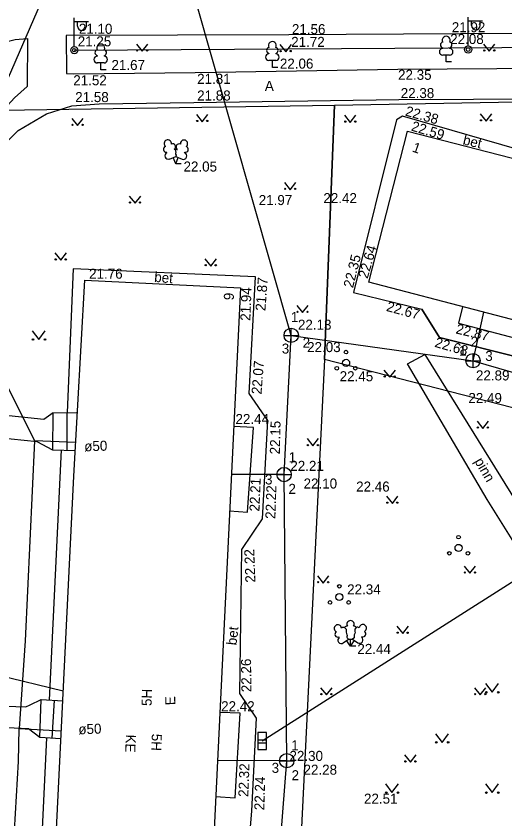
# Model space of a CAD drawing. Extents: x 714391 to 714584, y 6589993 to 6590151.
# Drawn here: x 714456.7 to 714490.9, y 6590036.2 to 6590092.2 of the extents above; entities that cross this region are included whole.
import ezdxf

# ---------------------------------------------------------------- set-up
doc = ezdxf.new("R2010")
doc.units = 0
for name, color, linetype in [('HALJASTUS', 7, 'Continuous'), ('HOONE', 7, 'Continuous'), ('HOONEDET', 7, 'Continuous'), ('KKAEV', 7, 'Continuous'), ('KORGUS', 7, 'Continuous'), ('KTRASS', 7, 'Continuous'), ('MPKAABEL', 7, 'Continuous'), ('POST', 7, 'Continuous'), ('PUU', 7, 'Continuous'), ('TEE', 7, 'Continuous'), ('TORU NR', 7, 'Continuous'), ('VTRASS', 7, 'Continuous'), ('Слой 1', 7, 'Continuous')]:
    doc.layers.add(name, color=color, linetype=linetype)

msp = doc.modelspace()

# ---------------------------------------------------------------- linework, layer by layer
at = {"layer": 'HALJASTUS'}
for p, q in [((714465.147, 6590090.247), (714465.552, 6590089.742)), ((714465.552, 6590089.742), (714465.947, 6590090.247)), ((714475.171, 6590090.202), (714475.576, 6590089.697)), ((714475.576, 6590089.697), (714475.971, 6590090.202)), ((714489.394, 6590090.247), (714489.799, 6590089.742)), ((714489.799, 6590089.742), (714490.194, 6590090.247)), ((714460.632, 6590085.055), (714461.037, 6590084.55)), ((714461.037, 6590084.55), (714461.432, 6590085.055)), ((714469.346, 6590085.326), (714469.751, 6590084.821)), ((714469.751, 6590084.821), (714470.146, 6590085.326)), ((714479.686, 6590085.28), (714480.091, 6590084.775)), ((714480.091, 6590084.775), (714480.486, 6590085.28)), ((714489.169, 6590085.371), (714489.574, 6590084.866)), ((714489.574, 6590084.866), (714489.969, 6590085.371)), ((714475.487, 6590080.584), (714475.892, 6590080.079)), ((714475.892, 6590080.079), (714476.287, 6590080.584)), ((714464.65, 6590079.636), (714465.055, 6590079.131)), ((714465.055, 6590079.131), (714465.45, 6590079.636)), ((714459.458, 6590075.663), (714459.863, 6590075.158)), ((714459.863, 6590075.158), (714460.258, 6590075.663)), ((714469.933, 6590075.256), (714470.338, 6590074.751)), ((714470.338, 6590074.751), (714470.733, 6590075.256)), ((714476.345, 6590072.005), (714476.75, 6590071.5)), ((714476.75, 6590071.5), (714477.145, 6590072.005)), ((714457.867, 6590070.227), (714458.33, 6590069.62)), ((714458.33, 6590069.62), (714458.776, 6590070.227)), ((714482.441, 6590067.49), (714482.846, 6590066.985)), ((714482.846, 6590066.985), (714483.241, 6590067.49)), ((714488.943, 6590063.923), (714489.348, 6590063.418)), ((714489.348, 6590063.418), (714489.743, 6590063.923)), ((714477.067, 6590062.704), (714477.472, 6590062.199)), ((714477.472, 6590062.199), (714477.867, 6590062.704)), ((714482.621, 6590058.685), (714483.026, 6590058.18)), ((714483.026, 6590058.18), (714483.421, 6590058.685)), ((714488.04, 6590053.808), (714488.445, 6590053.303)), ((714488.445, 6590053.303), (714488.84, 6590053.808)), ((714477.79, 6590053.131), (714478.195, 6590052.626)), ((714478.195, 6590052.626), (714478.59, 6590053.131)), ((714483.344, 6590049.609), (714483.749, 6590049.104)), ((714483.749, 6590049.104), (714484.144, 6590049.609)), ((714478.016, 6590045.32), (714478.421, 6590044.815)), ((714478.421, 6590044.815), (714478.816, 6590045.32)), ((714488.762, 6590045.32), (714489.167, 6590044.815)), ((714489.167, 6590044.815), (714489.562, 6590045.32)), ((714489.537, 6590045.607), (714490, 6590045)), ((714490, 6590045), (714490.446, 6590045.607)), ((714486.037, 6590042.107), (714486.5, 6590041.5)), ((714486.5, 6590041.5), (714486.946, 6590042.107)), ((714483.886, 6590040.624), (714484.291, 6590040.119)), ((714484.291, 6590040.119), (714484.686, 6590040.624)), ((714482.537, 6590038.607), (714483, 6590038)), ((714483, 6590038), (714483.446, 6590038.607)), ((714489.537, 6590038.607), (714490, 6590038)), ((714490, 6590038), (714490.446, 6590038.607))]:
    msp.add_line(p, q, dxfattribs=at)
for centre, radius in [((714465.199, 6590089.798), 0.0428), ((714465.899, 6590089.798), 0.0452), ((714475.223, 6590089.752), 0.0428), ((714475.923, 6590089.752), 0.0452), ((714489.446, 6590089.798), 0.0428), ((714490.146, 6590089.798), 0.0452), ((714469.398, 6590084.876), 0.0428), ((714470.098, 6590084.876), 0.0452), ((714489.221, 6590084.921), 0.0428), ((714489.921, 6590084.921), 0.0452), ((714460.684, 6590084.605), 0.0428), ((714461.384, 6590084.605), 0.0452), ((714479.738, 6590084.831), 0.0428), ((714480.438, 6590084.831), 0.0452), ((714475.539, 6590080.135), 0.0428), ((714476.239, 6590080.135), 0.0452), ((714464.702, 6590079.186), 0.0428), ((714465.402, 6590079.186), 0.0452), ((714459.51, 6590075.213), 0.0428), ((714460.21, 6590075.213), 0.0452), ((714469.985, 6590074.807), 0.0428), ((714470.685, 6590074.807), 0.0452), ((714476.397, 6590071.556), 0.0428), ((714477.097, 6590071.556), 0.0452), ((714457.929, 6590069.62), 0.055), ((714458.758, 6590069.62), 0.055), ((714479.793, 6590068.742), 0.125), ((714479.793, 6590067.992), 0.25), ((714479.143, 6590067.617), 0.125), ((714480.443, 6590067.617), 0.125), ((714482.493, 6590067.04), 0.0428), ((714483.193, 6590067.04), 0.0452), ((714488.995, 6590063.473), 0.0428), ((714489.695, 6590063.473), 0.0452), ((714477.119, 6590062.254), 0.0428), ((714477.819, 6590062.254), 0.0452), ((714482.673, 6590058.235), 0.0428), ((714483.373, 6590058.235), 0.0452), ((714487.654, 6590055.825), 0.125), ((714487.654, 6590055.075), 0.25), ((714487.004, 6590054.7), 0.125), ((714488.304, 6590054.7), 0.125), ((714488.092, 6590053.359), 0.0428), ((714488.792, 6590053.359), 0.0452), ((714477.842, 6590052.681), 0.0428), ((714478.542, 6590052.681), 0.0452), ((714479.322, 6590052.398), 0.125), ((714479.322, 6590051.648), 0.25), ((714478.672, 6590051.273), 0.125), ((714479.972, 6590051.273), 0.125), ((714483.396, 6590049.159), 0.0428), ((714484.096, 6590049.159), 0.0452), ((714478.068, 6590044.87), 0.0428), ((714478.768, 6590044.87), 0.0452), ((714488.814, 6590044.87), 0.0428), ((714489.514, 6590044.87), 0.0452), ((714489.599, 6590045), 0.055), ((714490.428, 6590045), 0.055), ((714486.099, 6590041.5), 0.055), ((714486.928, 6590041.5), 0.055), ((714483.938, 6590040.174), 0.0428), ((714484.638, 6590040.174), 0.0452), ((714482.599, 6590038), 0.055), ((714483.428, 6590038), 0.055), ((714489.599, 6590038), 0.055), ((714490.428, 6590038), 0.055)]:
    msp.add_circle(centre, radius, dxfattribs=at)
at = {"layer": 'HOONE'}
for points in [[(714459.73, 6590096.05), (714450.33, 6590074.44), (714440.46, 6590052.39), (714432.7, 6590035.24), (714421.56, 6590009.98), (714417.1, 6590000.12), (714413.783, 6589992.711)], [(714520.618, 6590063.399), (714481.385, 6590073.617), (714484.074, 6590084.17), (714523.648, 6590073.994), (714520.618, 6590063.399)], [(714450.33, 6590074.44), (714452.482, 6590073.562), (714456.5, 6590065.64), (714458.03, 6590062.54), (714457.37, 6590048.6), (714456.96, 6590042.47)], [(714458.41, 6590013.05), (714459.19, 6590027.87), (714460.78, 6590060.09), (714461.543, 6590073.769), (714472.409, 6590073.228), (714469.451, 6590012.441), (714458.41, 6590013.05)], [(714487.937, 6590071.893), (714487.647, 6590070.755), (714491.627, 6590069.716), (714491.916, 6590070.835)], [(714471.651, 6590057.661), (714472.916, 6590057.573), (714473.327, 6590063.471), (714471.938, 6590063.547)], [(714460.88, 6590062.44), (714458.03, 6590062.54)], [(714470.681, 6590037.715), (714472.056, 6590037.636), (714472.394, 6590043.535), (714470.967, 6590043.598)], [(714458.89, 6590022.24), (714455.84, 6590022.32), (714456.07, 6590025.65), (714456.9, 6590040.18), (714456.96, 6590042.47)], [(714456.96, 6590042.47), (714459.9, 6590042.3)]]:
    msp.add_lwpolyline(points, dxfattribs=at)
at = {"layer": 'HOONEDET'}
for points in [[(714458.41, 6590013.05), (714458.331, 6590012.184), (714470.239, 6590011.404), (714470.258, 6590012.413), (714471.076, 6590019.492), (714471.888, 6590019.599), (714472.556, 6590028.807), (714473.199, 6590036.732), (714473.546, 6590043.204), (714472.383, 6590044.92), (714472.511, 6590054.97), (714473.955, 6590057.113), (714474.332, 6590063.959), (714473.026, 6590065.846), (714473.46, 6590073.992), (714460.725, 6590074.548), (714460.31, 6590064.52)], [(714460.86, 6590061.85), (714459.31, 6590061.9), (714459.34, 6590064.51), (714460.97, 6590064.52)], [(714460.3, 6590061.87), (714460.31, 6590064.52)], [(714459.07, 6590044.46), (714459.91, 6590061.92)], [(714459.87, 6590041.74), (714458.41, 6590041.84), (714458.5, 6590044.49), (714460.01, 6590044.41)], [(714459.4, 6590044.44), (714459.24, 6590041.78)], [(714458.06, 6590024.25), (714458.89, 6590041.81)]]:
    msp.add_lwpolyline(points, dxfattribs=at)
at = {"layer": 'KKAEV'}
for p, q in [((714475.96, 6590069.411), (714475.96, 6590070.411)), ((714475.46, 6590069.911), (714476.46, 6590069.911)), ((714488.663, 6590067.645), (714488.663, 6590068.645)), ((714488.163, 6590068.145), (714489.163, 6590068.145)), ((714475.465, 6590059.699), (714475.465, 6590060.699)), ((714474.965, 6590060.199), (714475.965, 6590060.199)), ((714475.65, 6590039.724), (714475.65, 6590040.724)), ((714475.15, 6590040.224), (714476.15, 6590040.224))]:
    msp.add_line(p, q, dxfattribs=at)
for centre in [(714475.96, 6590069.911), (714488.663, 6590068.145), (714475.465, 6590060.199), (714475.65, 6590040.224)]:
    msp.add_circle(centre, 0.5, dxfattribs=at)
at = {"layer": 'KTRASS'}
for p, q in [((714475.96, 6590069.911), (714467.741, 6590098.726)), ((714488.663, 6590068.145), (714489.411, 6590071.527)), ((714475.465, 6590060.199), (714475.96, 6590069.911)), ((714475.96, 6590069.911), (714488.663, 6590068.145)), ((714488.663, 6590068.145), (714507.775, 6590062.609)), ((714475.465, 6590060.199), (714471.775, 6590060.206)), ((714475.65, 6590040.224), (714475.465, 6590060.199)), ((714475.65, 6590040.224), (714470.803, 6590040.234)), ((714474.411, 6590024.03), (714475.65, 6590040.224))]:
    msp.add_line(p, q, dxfattribs=at)
at = {"layer": 'MPKAABEL'}
for points in [[(714460.809, 6590089.818), (714516.791, 6590090.163), (714543.78, 6590090.458), (714574.561, 6590090.139)], [(714558.719, 6590063.793), (714557.614, 6590062.993), (714553.32, 6590062.662), (714527.694, 6590062.802), (714519.691, 6590062.433), (714508.979, 6590063.853), (714473.93, 6590041.599)]]:
    msp.add_lwpolyline(points, dxfattribs=at)
at = {"layer": 'POST'}
for p, q in [((714460.809, 6590090.068), (714460.809, 6590092.068)), ((714460.809, 6590091.818), (714461.809, 6590091.818)), ((714461.036, 6590091.497), (714461.036, 6590091.818)), ((714461.648, 6590091.497), (714461.648, 6590091.818)), ((714488.321, 6590090.113), (714488.321, 6590092.113)), ((714488.321, 6590091.863), (714489.321, 6590091.863)), ((714488.547, 6590091.542), (714488.547, 6590091.863)), ((714489.16, 6590091.542), (714489.16, 6590091.863)), ((714460.809, 6590089.818), (714460.809, 6590089.818)), ((714488.321, 6590089.863), (714488.321, 6590089.863)), ((714474.224, 6590042.198), (714473.627, 6590042.193)), ((714473.627, 6590042.193), (714473.637, 6590040.999)), ((714474.234, 6590041.004), (714474.224, 6590042.198)), ((714473.631, 6590041.677), (714474.228, 6590041.683)), ((714473.633, 6590041.46), (714474.23, 6590041.465)), ((714473.637, 6590040.999), (714474.234, 6590041.004))]:
    msp.add_line(p, q, dxfattribs=at)
for centre, radius in [((714460.809, 6590089.818), 0.25), ((714460.809, 6590089.818), 0.127), ((714488.321, 6590089.863), 0.25), ((714488.321, 6590089.863), 0.127)]:
    msp.add_circle(centre, radius, dxfattribs=at)
for centre in [(714461.342, 6590091.497), (714488.854, 6590091.542)]:
    msp.add_arc(centre, 0.306, 180, 0, dxfattribs=at)
at = {"layer": 'PUU'}
for p, q in [((714486.548, 6590089.975), (714486.548, 6590089.945)), ((714487.028, 6590089.975), (714487.028, 6590089.945)), ((714462.415, 6590089.43), (714462.415, 6590089.4)), ((714462.895, 6590089.43), (714462.895, 6590089.4)), ((714474.405, 6590089.595), (714474.405, 6590089.565)), ((714474.885, 6590089.595), (714474.885, 6590089.565)), ((714487.028, 6590089.47), (714486.548, 6590089.47)), ((714486.788, 6590088.995), (714486.788, 6590089.47)), ((714462.895, 6590088.925), (714462.415, 6590088.925)), ((714462.655, 6590088.45), (714462.655, 6590088.925)), ((714474.885, 6590089.09), (714474.405, 6590089.09)), ((714474.645, 6590088.615), (714474.645, 6590089.09)), ((714487.168, 6590088.995), (714486.788, 6590088.995)), ((714463.035, 6590088.45), (714462.655, 6590088.45)), ((714475.025, 6590088.615), (714474.645, 6590088.615)), ((714467.276, 6590082.664), (714467.261, 6590082.704)), ((714467.806, 6590082.874), (714467.791, 6590082.909)), ((714467.991, 6590082.869), (714468.006, 6590082.909)), ((714468.516, 6590082.654), (714468.531, 6590082.694)), ((714467.451, 6590082.219), (714467.896, 6590082.394)), ((714467.891, 6590081.884), (714467.716, 6590082.324)), ((714467.891, 6590081.884), (714468.071, 6590082.324)), ((714467.896, 6590082.394), (714468.336, 6590082.214)), ((714468.271, 6590081.884), (714467.891, 6590081.884)), ((714479.319, 6590048.831), (714479.294, 6590048.866)), ((714479.594, 6590048.446), (714479.954, 6590048.701)), ((714480.104, 6590048.226), (714479.829, 6590048.611)), ((714479.954, 6590048.701), (714480.249, 6590048.701)), ((714480.104, 6590048.226), (714480.104, 6590048.701)), ((714480.104, 6590048.226), (714480.374, 6590048.616)), ((714480.249, 6590048.701), (714480.609, 6590048.456)), ((714480.879, 6590048.846), (714480.899, 6590048.881)), ((714480.484, 6590048.226), (714480.104, 6590048.226))]:
    msp.add_line(p, q, dxfattribs=at)
for points in [[(714467.896, 6590082.889), (714467.876, 6590082.814), (714467.876, 6590082.794), (714467.886, 6590082.764), (714467.906, 6590082.729), (714467.911, 6590082.709), (714467.896, 6590082.674), (714467.871, 6590082.624), (714467.866, 6590082.599), (714467.871, 6590082.584), (714467.881, 6590082.554), (714467.916, 6590082.494), (714467.921, 6590082.474), (714467.916, 6590082.454), (714467.901, 6590082.419), (714467.896, 6590082.394)], [(714479.689, 6590049.511), (714479.794, 6590049.411), (714479.809, 6590049.381), (714479.809, 6590049.326), (714479.794, 6590049.236), (714479.794, 6590049.191), (714479.814, 6590049.111), (714479.854, 6590049.021), (714479.864, 6590048.976), (714479.859, 6590048.931), (714479.844, 6590048.866), (714479.844, 6590048.836), (714479.864, 6590048.796), (714479.889, 6590048.766), (714479.954, 6590048.701)], [(714480.509, 6590049.526), (714480.414, 6590049.411), (714480.399, 6590049.381), (714480.399, 6590049.326), (714480.414, 6590049.236), (714480.419, 6590049.191), (714480.399, 6590049.111), (714480.359, 6590049.021), (714480.349, 6590048.976), (714480.354, 6590048.931), (714480.369, 6590048.866), (714480.369, 6590048.836), (714480.349, 6590048.796), (714480.324, 6590048.766), (714480.254, 6590048.701)]]:
    msp.add_lwpolyline(points, dxfattribs=at)
for centre, radius, start, end in [((714486.788, 6590090.515), 0.277, 332.5799, 207.4201), ((714462.655, 6590089.97), 0.277, 332.5799, 207.4201), ((714474.455, 6590089.803), 0.212, 105.2441, 257.079), ((714474.645, 6590090.135), 0.277, 332.5799, 207.4201), ((714474.835, 6590089.803), 0.212, 282.921, 74.7559), ((714486.55, 6590089.708), 0.237, 90, 270), ((714486.598, 6590090.183), 0.212, 105.2441, 257.079), ((714487.025, 6590089.708), 0.237, 270, 90), ((714486.978, 6590090.183), 0.212, 282.921, 74.7559), ((714462.417, 6590089.163), 0.237, 90, 270), ((714462.465, 6590089.638), 0.212, 105.2441, 257.079), ((714462.892, 6590089.163), 0.237, 270, 90), ((714462.845, 6590089.638), 0.212, 282.921, 74.7559), ((714474.407, 6590089.328), 0.237, 90, 270), ((714474.882, 6590089.328), 0.237, 270, 90), ((714467.334, 6590083.298), 0.256, 111.5027, 232.5173), ((714467.334, 6590083.298), 0.256, 350.4856, 111.5002), ((714467.677, 6590083.076), 0.202, 305.1345, 116.705), ((714468.124, 6590083.072), 0.202, 62.412, 233.9825), ((714468.47, 6590083.289), 0.256, 67.6168, 188.6314), ((714468.47, 6590083.289), 0.256, 306.5997, 67.6143), ((714467.235, 6590082.902), 0.202, 106.2979, 277.8684), ((714467.365, 6590082.442), 0.237, 111.5014, 291.5004), ((714467.895, 6590082.651), 0.237, 66.7655, 111.5015), ((714468.426, 6590082.434), 0.237, 247.6166, 67.6155), ((714468.563, 6590082.892), 0.202, 261.2486, 72.8191), ((714479.221, 6590049.463), 0.256, 125.5389, 246.5536), ((714479.221, 6590049.463), 0.256, 4.5218, 125.5364), ((714479.866, 6590049.414), 0.202, 84.7965, 150.2995), ((714480.104, 6590049.746), 0.256, 90.0013, 211.0159), ((714480.104, 6590049.746), 0.256, 328.9841, 89.9987), ((714480.341, 6590049.414), 0.202, 34.3857, 95.2035), ((714480.964, 6590049.479), 0.256, 55.522, 176.5367), ((714480.964, 6590049.479), 0.256, 294.5049, 55.5195), ((714479.221, 6590049.054), 0.202, 120.3342, 291.9047), ((714479.607, 6590049.33), 0.202, 65.2382, 130.7412), ((714480.58, 6590049.339), 0.202, 50.3173, 111.1351), ((714480.972, 6590049.07), 0.202, 249.1538, 60.7243), ((714479.458, 6590048.64), 0.237, 125.5377, 305.5366), ((714480.742, 6590048.652), 0.237, 235.5219, 55.5208)]:
    msp.add_arc(centre, radius, start, end, dxfattribs=at)
at = {"layer": 'TEE'}
for points in [[(714573.651, 6590091.235), (714563.941, 6590091.279), (714547.616, 6590091.212), (714515.821, 6590091.083), (714495.803, 6590091.003), (714475.803, 6590090.885), (714460.229, 6590090.83)], [(714439.98, 6590066.01), (714446.14, 6590079.41), (714447.61, 6590082.54), (714448.99, 6590084.86), (714450.43, 6590086.9), (714452.47, 6590088.66), (714455.19, 6590090.19), (714456.67, 6590090.57), (714457.54, 6590090.63)], [(714457.54, 6590090.63), (714457.51, 6590087.28), (714456.63, 6590086.49), (714453.85, 6590083.48), (714451.12, 6590079.51), (714448.27, 6590074.4), (714444.05, 6590065.54), (714439.98, 6590066.01)], [(714460.229, 6590090.83), (714460.256, 6590088.179), (714460.777, 6590088.177), (714469.248, 6590088.252), (714483.421, 6590088.5), (714493.771, 6590088.564), (714493.794, 6590090.794), (714493.796, 6590090.991)], [(714459.34, 6590064.51), (714458.67, 6590064.05), (714447.983, 6590065.15), (714447.715, 6590065.177), (714445.65, 6590065.39), (714446.67, 6590067.85), (714448.36, 6590071.52), (714451, 6590076.28), (714452.73, 6590079.02), (714455.01, 6590082.32), (714456.89, 6590084.2), (714458.87, 6590085.38), (714460.64, 6590085.94), (714462.556, 6590086.069), (714469.16, 6590086.164), (714483.473, 6590086.366), (714493.922, 6590086.42), (714493.109, 6590083.292)], [(714492.924, 6590082.556), (714483.739, 6590085.22), (714483.316, 6590084.953), (714480.306, 6590072.893), (714485.078, 6590071.74), (714486.316, 6590069.766), (714491.895, 6590068.37), (714493.892, 6590069.273), (714504.243, 6590066.794), (714505.962, 6590064.851), (714511.02, 6590063.567), (714513.67, 6590064.358), (714521.189, 6590062.359)], [(714493.892, 6590069.273), (714491.895, 6590068.37), (714486.316, 6590069.766), (714485.078, 6590071.74)], [(714503.783, 6590036.391), (714498.601, 6590044.145), (714494.073, 6590051.394), (714489.657, 6590058.462), (714484.091, 6590067.913), (714485.295, 6590068.584), (714495.449, 6590052.222), (714495.743, 6590051.781), (714495.449, 6590052.222), (714505.314, 6590037.415)], [(714459.31, 6590061.9), (714458.22, 6590062.47), (714447.303, 6590063.601), (714447.271, 6590063.604), (714445.09, 6590063.83), (714436.59, 6590044.66), (714438.563, 6590044.596), (714438.967, 6590044.582), (714457.41, 6590043.98), (714457.72, 6590044.12), (714458.5, 6590044.49)], [(714458.41, 6590041.84), (714457.61, 6590042.45), (714451.01, 6590042.74), (714438.326, 6590043.121), (714437.835, 6590043.135), (714436.01, 6590043.19), (714428.72, 6590026.84), (714430.208, 6590026.691), (714430.977, 6590026.614), (714435.5, 6590026.16), (714448.72, 6590024.98), (714455.07, 6590024.44), (714457.48, 6590024.27)]]:
    msp.add_lwpolyline(points, dxfattribs=at)
at = {"layer": 'VTRASS'}
msp.add_line((714438.963, 6590050.251), (714460.04, 6590045.1), dxfattribs=at)
at = {"layer": 'Слой 1'}
for points in [[(714478.99, 6590085.97), (714532.4, 6590086.95), (714527.28, 6590069.21), (714523.84, 6590056.54), (714478.28, 6590068.22)], [(714455.78, 6590085.63), (714478.99, 6590085.97), (714478.28, 6590068.22), (714475.39, 6590009.54), (714423.1, 6590012.8)]]:
    msp.add_lwpolyline(points, close=True, dxfattribs=at)

# ---------------------------------------------------------------- texts
at = {"layer": 'HOONE'}
for s, rotation, p in [('1', 340.7456, (714484.367, 6590082.753)), ('9', 86.33, (714471.939, 6590072.344)), ('5H', 88.5478, (714466.207, 6590044.034)), ('E', 91.6372, (714467.87, 6590044.105)), ('KE', 267.5848, (714464.415, 6590042.061)), ('5H', 267.5848, (714466.228, 6590042.117))]:
    msp.add_text(s, height=0.7, rotation=rotation, dxfattribs=at).set_placement(p)
at = {"layer": 'HOONEDET'}
for rotation, p in [(346.6797, (714487.909, 6590083.247)), (355.092, (714466.371, 6590073.653)), (83.7787, (714472.138, 6590048.255))]:
    msp.add_text('bet', height=0.7, rotation=rotation, dxfattribs=at).set_placement(p)
at = {"layer": 'KORGUS'}
for s, p in [('21.10', (714461.125, 6590090.96)), ('21.56', (714476.01, 6590090.934)), ('21.92', (714487.179, 6590091.068)), ('21.25', (714461.047, 6590090.084)), ('21.72', (714475.959, 6590090.044)), ('22.08', (714487.068, 6590090.248)), ('21.67', (714463.404, 6590088.432)), ('22.06', (714475.168, 6590088.529)), ('22.35', (714483.425, 6590087.748)), ('21.52', (714460.736, 6590087.368)), ('21.81', (714469.388, 6590087.466)), ('22.38', (714483.613, 6590086.472)), ('21.58', (714460.87, 6590086.193)), ('21.88', (714469.39, 6590086.304)), ('22.05', (714468.437, 6590081.346)), ('22.42', (714478.209, 6590079.142)), ('21.97', (714473.691, 6590079.006)), ('21.76', (714461.841, 6590073.864)), ('22.13', (714476.431, 6590070.307)), ('22.03', (714477.072, 6590068.744)), ('22.45', (714479.346, 6590066.709)), ('22.89', (714488.867, 6590066.767)), ('22.49', (714488.338, 6590065.19)), ('22.44', (714472.067, 6590063.724)), ('22.21', (714475.898, 6590060.453)), ('22.10', (714476.824, 6590059.221)), ('22.46', (714480.497, 6590059.008)), ('22.34', (714479.868, 6590051.833)), ('22.44', (714480.582, 6590047.677)), ('22.42', (714471.066, 6590043.675)), ('22.30', (714475.839, 6590040.209)), ('22.28', (714476.821, 6590039.248)), ('22.51', (714481.046, 6590037.226))]:
    msp.add_text(s, height=0.7, dxfattribs=at).set_placement(p)
for s, rotation, p in [('22.38', 344.1808, (714483.88, 6590085.265)), ('22.59', 343.3365, (714484.295, 6590084.215)), ('22.64', 73.6731, (714481.294, 6590073.832)), ('22.35', 75.8745, (714480.273, 6590073.18)), ('21.87', 85.6777, (714474.155, 6590071.595)), ('21.94', 87.8562, (714473.104, 6590070.914)), ('22.67', 344.6907, (714482.562, 6590071.628)), ('22.87', 346.5941, (714487.418, 6590070.054)), ('22.68', 343.9313, (714485.939, 6590069.121)), ('22.07', 85.6013, (714473.882, 6590065.776)), ('22.15', 88.6521, (714475.165, 6590061.599)), ('22.21', 87.763, (714473.739, 6590057.604)), ('22.22', 88.0651, (714474.851, 6590057.09)), ('22.22', 92.1081, (714473.46, 6590052.667)), ('22.26', 90.7192, (714473.183, 6590045.01)), ('22.32', 87.8701, (714472.962, 6590037.683)), ('22.24', 88.3727, (714474.078, 6590036.758))]:
    msp.add_text(s, height=0.7, rotation=rotation, dxfattribs=at).set_placement(p)
at = {"layer": 'TEE'}
msp.add_text('A', height=0.7, dxfattribs=at).set_placement((714474.12, 6590086.977))
msp.add_text('pinn', height=0.7, rotation=300.1735, dxfattribs=at).set_placement((714488.742, 6590061.131))
at = {"layer": 'TORU NR'}
for s, p in [('1', (714475.935, 6590070.844)), ('2', (714476.76, 6590069.052)), ('2', (714488.499, 6590069.117)), ('3', (714475.303, 6590068.64)), ('1', (714487.687, 6590068.498)), ('3', (714489.517, 6590068.125)), ('1', (714475.78, 6590061.05)), ('3', (714474.131, 6590059.504)), ('2', (714475.767, 6590058.847)), ('1', (714475.961, 6590040.948)), ('3', (714474.595, 6590039.376)), ('2', (714475.986, 6590038.86))]:
    msp.add_text(s, height=0.7, dxfattribs=at).set_placement(p)
for p in [(714461.513, 6590061.811), (714461.103, 6590042.061)]:
    msp.add_text('ø50', height=0.7, rotation=2.0348, dxfattribs=at).set_placement(p)

doc.saveas('drawing.dxf')
